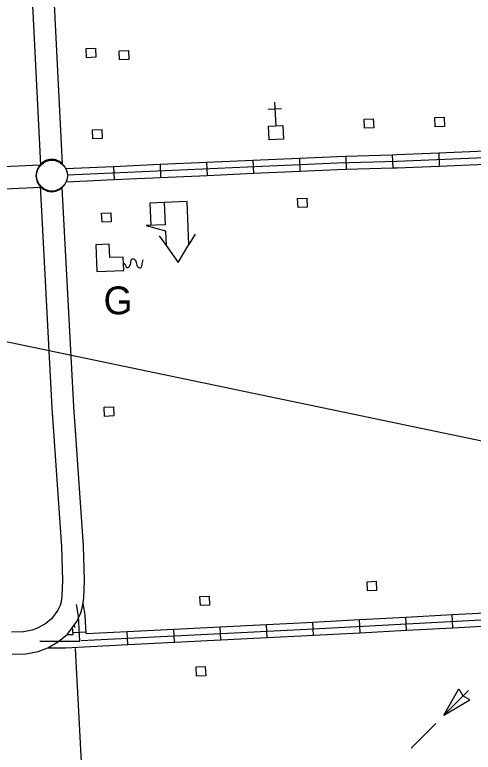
# Model space of a CAD drawing. Extents: x -0.3 to 2.65, y 0 to 1.9.
# Drawn here: x 0.8173 to 0.8796, y 0.2167 to 0.3171 of the extents above; entities that cross this region are included whole.
import ezdxf

# ---------------------------------------------------------------- set-up
doc = ezdxf.new("R2010")
doc.units = 0
for name, color, linetype in [('Default', 7, 'Continuous'), ('Level 12', 7, 'Continuous'), ('Level 15', 7, 'Continuous'), ('Level 19', 7, 'Continuous'), ('Level 20', 7, 'Continuous'), ('Level 21', 7, 'Continuous'), ('Level 24', 7, 'Continuous'), ('Level 32', 7, 'Continuous')]:
    doc.layers.add(name, color=color, linetype=linetype)

msp = doc.modelspace()

# ---------------------------------------------------------------- linework, layer by layer
at = {"layer": 'Default'}
msp.add_lwpolyline([(0.9717723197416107, 0.24008859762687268), (0.7329330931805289, 0.28998176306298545), (0.8008303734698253, 0.28385595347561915)], dxfattribs=at)
at = {"layer": 'Level 12'}
for p, q in [((0.8756462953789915, 0.22178944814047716), (0.8776815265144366, 0.2253564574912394)), ((0.8776815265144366, 0.2253564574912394), (0.8782330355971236, 0.22441238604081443)), ((0.8756462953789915, 0.22178944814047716), (0.8791923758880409, 0.22386094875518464)), ((0.8791923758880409, 0.22386094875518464), (0.8782433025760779, 0.2244024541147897))]:
    msp.add_line(p, q, dxfattribs=at)
for points in [[(0.8789797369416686, 0.22515704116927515), (0.8756461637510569, 0.22178930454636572)], [(0.8745349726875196, 0.22066672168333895), (0.8712013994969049, 0.21729898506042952)]]:
    msp.add_lwpolyline(points, dxfattribs=at)
at = {"layer": 'Level 15'}
for p, q in [((0.8749442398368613, 0.2983256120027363), (0.8750168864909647, 0.2965321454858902)), ((0.849687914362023, 0.297331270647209), (0.8497682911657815, 0.29553815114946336)), ((0.8559997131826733, 0.29761419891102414), (0.8560800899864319, 0.29582107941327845)), ((0.8623244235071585, 0.2978811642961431), (0.8623797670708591, 0.2960870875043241)), ((0.8686395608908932, 0.2980759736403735), (0.8686949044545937, 0.29628189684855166)), ((0.8307525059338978, 0.2964824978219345), (0.8308328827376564, 0.2946893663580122)), ((0.8370643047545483, 0.29676542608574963), (0.8371446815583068, 0.2949722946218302)), ((0.8433761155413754, 0.29704835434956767), (0.8434564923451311, 0.2952552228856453)), ((0.8705622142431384, 0.23334725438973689), (0.8704659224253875, 0.23513959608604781)), ((0.876871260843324, 0.23368622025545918), (0.8767749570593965, 0.23547856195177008)), ((0.8516315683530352, 0.232346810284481), (0.8515406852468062, 0.2341394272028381)), ((0.8579441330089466, 0.23266931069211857), (0.8578478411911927, 0.23446165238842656)), ((0.8642531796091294, 0.23300827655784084), (0.8641568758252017, 0.23480061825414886)), ((0.8252134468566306, 0.23303609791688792), (0.8270055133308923, 0.23313735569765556)), ((0.8327014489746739, 0.2313871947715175), (0.8326105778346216, 0.2331798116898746)), ((0.8390114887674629, 0.2317070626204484), (0.8389206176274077, 0.23349969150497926)), ((0.8453215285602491, 0.23202693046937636), (0.8452306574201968, 0.23381955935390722))]:
    msp.add_line(p, q, dxfattribs=at)
for points in [[(0.8244801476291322, 0.29531955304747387), (0.8611742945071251, 0.29696436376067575), (0.8692683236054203, 0.2972140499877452), (0.882270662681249, 0.2977407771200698), (0.8853113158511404, 0.29801934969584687), (0.8906485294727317, 0.29889195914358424), (0.9030999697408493, 0.2999709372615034), (0.907709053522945, 0.30024675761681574), (0.9127155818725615, 0.3004680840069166), (0.9267844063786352, 0.3012461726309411), (0.9394032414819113, 0.3020562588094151), (0.9431847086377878, 0.3023675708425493), (0.9483494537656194, 0.30301735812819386)], [(0.8686395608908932, 0.2980759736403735), (0.8692369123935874, 0.29809440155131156), (0.8749442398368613, 0.2983256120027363)], [(0.8749442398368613, 0.2983256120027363), (0.881257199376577, 0.29858135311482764)], [(0.8433761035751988, 0.29704834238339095), (0.8496879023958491, 0.297331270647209)], [(0.8496879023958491, 0.297331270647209), (0.8559997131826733, 0.29761419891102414)], [(0.8559997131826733, 0.29761419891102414), (0.8611409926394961, 0.29784465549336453), (0.8623244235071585, 0.2978811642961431)], [(0.8623244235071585, 0.2978811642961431), (0.8686395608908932, 0.2980759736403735)], [(0.8242242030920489, 0.2961898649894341), (0.8307524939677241, 0.2964824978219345)], [(0.8307524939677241, 0.2964824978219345), (0.8370643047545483, 0.29676542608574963)], [(0.837064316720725, 0.29676542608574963), (0.8433761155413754, 0.29704834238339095)], [(0.8623797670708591, 0.2960870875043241), (0.8686949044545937, 0.29628189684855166)], [(0.8686949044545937, 0.29628189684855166), (0.8693009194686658, 0.2963005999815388), (0.8750168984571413, 0.29653215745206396)], [(0.8750168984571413, 0.29653215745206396), (0.8813298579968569, 0.2967878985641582)], [(0.8371446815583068, 0.29497230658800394), (0.8434564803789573, 0.2952552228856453)], [(0.8434564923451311, 0.2952552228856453), (0.8497682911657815, 0.29553815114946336)], [(0.8497682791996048, 0.29553815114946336), (0.8560800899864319, 0.29582107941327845)], [(0.8560800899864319, 0.29582107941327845), (0.861208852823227, 0.2960509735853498), (0.8623797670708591, 0.2960870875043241)], [(0.8242888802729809, 0.29439603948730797), (0.8308328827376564, 0.29468937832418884)], [(0.8308328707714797, 0.29468937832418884), (0.8371446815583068, 0.29497230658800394)], [(0.8263468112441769, 0.2319470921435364), (0.857073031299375, 0.23350468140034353), (0.9086524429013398, 0.23627592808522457), (0.9498469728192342, 0.23921094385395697)], [(0.8270191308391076, 0.23289636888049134), (0.8268788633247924, 0.23537871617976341), (0.8266058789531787, 0.23705169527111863)], [(0.8261612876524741, 0.2318761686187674), (0.8259690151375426, 0.2352790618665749), (0.8257101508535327, 0.23686552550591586)], [(0.8641568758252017, 0.23480061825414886), (0.8704659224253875, 0.23513959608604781)], [(0.8704659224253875, 0.23513959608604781), (0.8767749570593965, 0.23547856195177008)], [(0.8767749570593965, 0.23547856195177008), (0.8830840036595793, 0.23581753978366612)], [(0.8452306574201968, 0.23381955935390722), (0.8515406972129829, 0.2341394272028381)], [(0.8515406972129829, 0.2341394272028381), (0.857025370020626, 0.23441746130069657), (0.8578478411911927, 0.23446165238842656)], [(0.8578478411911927, 0.23446165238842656), (0.8641568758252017, 0.23480061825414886)], [(0.876871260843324, 0.23368622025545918), (0.8831803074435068, 0.23402519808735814)], [(0.8252293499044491, 0.23275462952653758), (0.825172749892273, 0.23375630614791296)], [(0.8270191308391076, 0.23289636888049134), (0.8326105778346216, 0.2331798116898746)], [(0.8326105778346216, 0.2331798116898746), (0.8389206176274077, 0.23349969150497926)], [(0.8389206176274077, 0.23349969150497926), (0.8452306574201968, 0.23381955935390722)], [(0.8579441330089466, 0.23266931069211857), (0.8642531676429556, 0.23300827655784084)], [(0.8642531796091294, 0.23300827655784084), (0.870562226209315, 0.23334725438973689)], [(0.8705622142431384, 0.23334725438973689), (0.8768712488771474, 0.23368622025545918)], [(0.8243917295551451, 0.2327524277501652), (0.8252293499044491, 0.23275462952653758)], [(0.8390114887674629, 0.2317070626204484), (0.8453215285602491, 0.23202693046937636)], [(0.8453215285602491, 0.23202693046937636), (0.8516315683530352, 0.23234679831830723)], [(0.8516315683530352, 0.23234679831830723), (0.8571189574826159, 0.23262497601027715), (0.8579441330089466, 0.23266931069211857)], [(0.8207144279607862, 0.23186185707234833), (0.8261612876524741, 0.2318761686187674)], [(0.8217929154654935, 0.23095065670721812), (0.8242155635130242, 0.23095702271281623)], [(0.8242155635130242, 0.23095702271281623), (0.8327014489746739, 0.23138718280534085)], [(0.8327014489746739, 0.23138718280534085), (0.8390114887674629, 0.2317070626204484)]]:
    msp.add_lwpolyline(points, dxfattribs=at)
at = {"layer": 'Level 19'}
for points in [[(0.8270821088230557, 0.3112743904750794), (0.827027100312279, 0.31251868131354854), (0.8282750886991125, 0.3125738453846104), (0.8283300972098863, 0.31132956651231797)], [(0.8315573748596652, 0.3109765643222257), (0.8315023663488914, 0.312220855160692), (0.832750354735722, 0.31227601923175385), (0.8328053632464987, 0.31103174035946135)], [(0.8744805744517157, 0.3018778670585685), (0.874425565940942, 0.30312215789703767), (0.8756735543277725, 0.30317732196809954), (0.8757285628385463, 0.30193304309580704)], [(0.8648613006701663, 0.30166155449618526), (0.8648062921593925, 0.3029058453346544), (0.8660542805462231, 0.3029610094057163), (0.8661092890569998, 0.3017167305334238)], [(0.8279437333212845, 0.30021405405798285), (0.8278887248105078, 0.3014583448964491), (0.8291367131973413, 0.3015135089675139), (0.829191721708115, 0.3002692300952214)], [(0.8558230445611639, 0.2908750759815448), (0.8557680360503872, 0.29211936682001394), (0.8570160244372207, 0.2921745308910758), (0.8570710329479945, 0.2909302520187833)], [(0.8291713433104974, 0.2888811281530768), (0.8291163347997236, 0.2901254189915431), (0.8303643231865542, 0.29018058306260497), (0.830419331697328, 0.2889363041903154)], [(0.8295174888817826, 0.26245325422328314), (0.8294648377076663, 0.263697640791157), (0.8307129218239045, 0.263750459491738), (0.8307655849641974, 0.2625060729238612)], [(0.8652563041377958, 0.23870717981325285), (0.8652036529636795, 0.23995156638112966), (0.8664517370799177, 0.2400043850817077), (0.8665044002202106, 0.23875999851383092)], [(0.8425438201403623, 0.2366995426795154), (0.8424911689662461, 0.2379439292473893), (0.8437392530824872, 0.23799674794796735), (0.8437919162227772, 0.23675236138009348)], [(0.8420209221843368, 0.22709906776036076), (0.8419682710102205, 0.22834345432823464), (0.8432163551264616, 0.2283962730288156), (0.8432690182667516, 0.2271518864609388)]]:
    msp.add_lwpolyline(points, close=True, dxfattribs=at)
at = {"layer": 'Level 20'}
for points in [[(0.825418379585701, 0.2339778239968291), (0.8254321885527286, 0.23370078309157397)], [(0.8286594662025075, 0.17250891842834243), (0.8255765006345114, 0.23086770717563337)]]:
    msp.add_lwpolyline(points, dxfattribs=at)
at = {"layer": 'Level 21'}
for points in [[(0.8192582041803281, 0.3274396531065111), (0.8207941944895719, 0.29670443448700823)], [(0.8237835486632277, 0.2968227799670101), (0.8222460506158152, 0.32758839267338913)], [(0.8207288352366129, 0.2966461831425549), (0.7990293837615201, 0.2956388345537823)], [(0.7991931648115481, 0.2926516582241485), (0.8208573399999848, 0.29365736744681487)], [(0.8207441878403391, 0.29381466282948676), (0.822357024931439, 0.2635949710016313), (0.8236732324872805, 0.24469353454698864), (0.8237967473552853, 0.24011803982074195), (0.8237183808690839, 0.2379746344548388), (0.8236041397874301, 0.23720309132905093), (0.8234747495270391, 0.23673131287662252), (0.8231654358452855, 0.23606713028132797), (0.8222888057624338, 0.2348952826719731), (0.821522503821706, 0.23426143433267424), (0.820504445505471, 0.23366000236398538), (0.8196590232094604, 0.2333337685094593), (0.8185009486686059, 0.23310757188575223), (0.8168505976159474, 0.23307155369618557)], [(0.8169564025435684, 0.23008161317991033), (0.8188226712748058, 0.23012234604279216), (0.8204906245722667, 0.2304481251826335), (0.8218126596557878, 0.23095827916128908), (0.8232473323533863, 0.23180583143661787), (0.824470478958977, 0.23281757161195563), (0.8257465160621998, 0.23452327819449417), (0.8262930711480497, 0.23569693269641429), (0.8265369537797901, 0.236586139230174), (0.8267018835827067, 0.23770005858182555), (0.8267897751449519, 0.24010372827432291), (0.8266619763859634, 0.24483787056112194), (0.8253430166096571, 0.263778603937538), (0.8237518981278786, 0.29359151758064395)]]:
    msp.add_lwpolyline(points, dxfattribs=at)
for centre, radius, start, end in [((0.8223421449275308, 0.2954179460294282), 0.002012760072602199, 44.263875, 140.27031666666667), ((0.8223450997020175, 0.29521850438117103), 0.0021565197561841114, 138.54519444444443, 226.37866111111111), ((0.8223504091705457, 0.29508285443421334), 0.002046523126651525, 218.29284722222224, 313.22103055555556)]:
    msp.add_arc(centre, radius, start, end, dxfattribs=at)
at = {"layer": 'Level 24'}
msp.add_circle((0.822365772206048, 0.29522478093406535), 0.002094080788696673, dxfattribs=at)
at = {"layer": 'Level 32'}
for p, q in [((0.8526390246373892, 0.30522091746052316), (0.8527813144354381, 0.30200219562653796)), ((0.8517820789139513, 0.30428469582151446), (0.8535752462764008, 0.30436397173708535)), ((0.8418228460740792, 0.2872642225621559), (0.8409868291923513, 0.2858532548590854)), ((0.8369201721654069, 0.2870475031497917), (0.8378774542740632, 0.28571579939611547))]:
    msp.add_line(p, q, dxfattribs=at)
for points in [[(0.8518930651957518, 0.30009391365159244), (0.8518106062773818, 0.3019592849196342), (0.8537453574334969, 0.30204480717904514), (0.8538278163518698, 0.30017944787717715)], [(0.8407280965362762, 0.29170616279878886), (0.8376187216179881, 0.29156871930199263), (0.8377527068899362, 0.28853789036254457), (0.8351672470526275, 0.288423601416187), (0.8377891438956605, 0.2877136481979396), (0.8378774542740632, 0.28571579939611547), (0.8395372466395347, 0.2834067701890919), (0.8409868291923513, 0.2858532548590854)], [(0.8283265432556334, 0.2858149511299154), (0.8284882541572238, 0.2821568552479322), (0.832146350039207, 0.28231856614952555), (0.8320654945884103, 0.28414760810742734), (0.8302364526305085, 0.28406675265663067), (0.8301555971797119, 0.28589580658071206)]]:
    msp.add_lwpolyline(points, close=True, dxfattribs=at)
for points in [[(0.8376187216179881, 0.29156871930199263), (0.8356519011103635, 0.291481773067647), (0.8357858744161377, 0.2884509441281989)], [(0.832113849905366, 0.2832912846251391), (0.8321409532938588, 0.28328180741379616), (0.8321680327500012, 0.28327235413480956), (0.8322011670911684, 0.2832471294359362), (0.832228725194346, 0.2832270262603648), (0.8322453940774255, 0.2832117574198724), (0.8322678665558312, 0.28318606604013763), (0.8322847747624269, 0.28316548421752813), (0.8323019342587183, 0.2831395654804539), (0.8323309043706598, 0.2830875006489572), (0.832348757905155, 0.28304561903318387), (0.8323666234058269, 0.2830037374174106), (0.8323856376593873, 0.28293525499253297), (0.832415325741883, 0.2828672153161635), (0.8324614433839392, 0.2827892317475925), (0.8325223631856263, 0.2827385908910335), (0.8325983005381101, 0.28270993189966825), (0.8326837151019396, 0.2827083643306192), (0.8327672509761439, 0.28274942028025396), (0.8328651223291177, 0.2828284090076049), (0.8329594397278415, 0.2829872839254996), (0.8330220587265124, 0.28313939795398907), (0.8330723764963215, 0.2833283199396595), (0.8330931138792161, 0.28346260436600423), (0.8331048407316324, 0.28355913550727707), (0.8331214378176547, 0.2836665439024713), (0.8331794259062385, 0.28380246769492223), (0.8332714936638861, 0.2838918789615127), (0.8333876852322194, 0.28391836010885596), (0.8335009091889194, 0.28389135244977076), (0.8336000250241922, 0.283821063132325), (0.8336952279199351, 0.2837185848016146), (0.8337596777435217, 0.28358808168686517), (0.8338276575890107, 0.2833777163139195), (0.833878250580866, 0.28319859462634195), (0.8339177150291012, 0.28302964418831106), (0.8339548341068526, 0.28291391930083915), (0.8340398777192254, 0.2828003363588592), (0.834172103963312, 0.2827048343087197), (0.8343010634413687, 0.28268384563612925), (0.8344179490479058, 0.2826943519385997), (0.8345070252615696, 0.2827303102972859), (0.8346069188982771, 0.28288407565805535), (0.834650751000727, 0.2830993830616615), (0.8346499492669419, 0.28323804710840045), (0.8346598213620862, 0.28337716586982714), (0.8347089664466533, 0.28359270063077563), (0.8347711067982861, 0.283755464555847)]]:
    msp.add_lwpolyline(points, dxfattribs=at)

# ---------------------------------------------------------------- texts
msp.add_text('G', height=0.0037908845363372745, dxfattribs=at).set_placement((0.8293782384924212, 0.27634672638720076))

doc.saveas('drawing.dxf')
